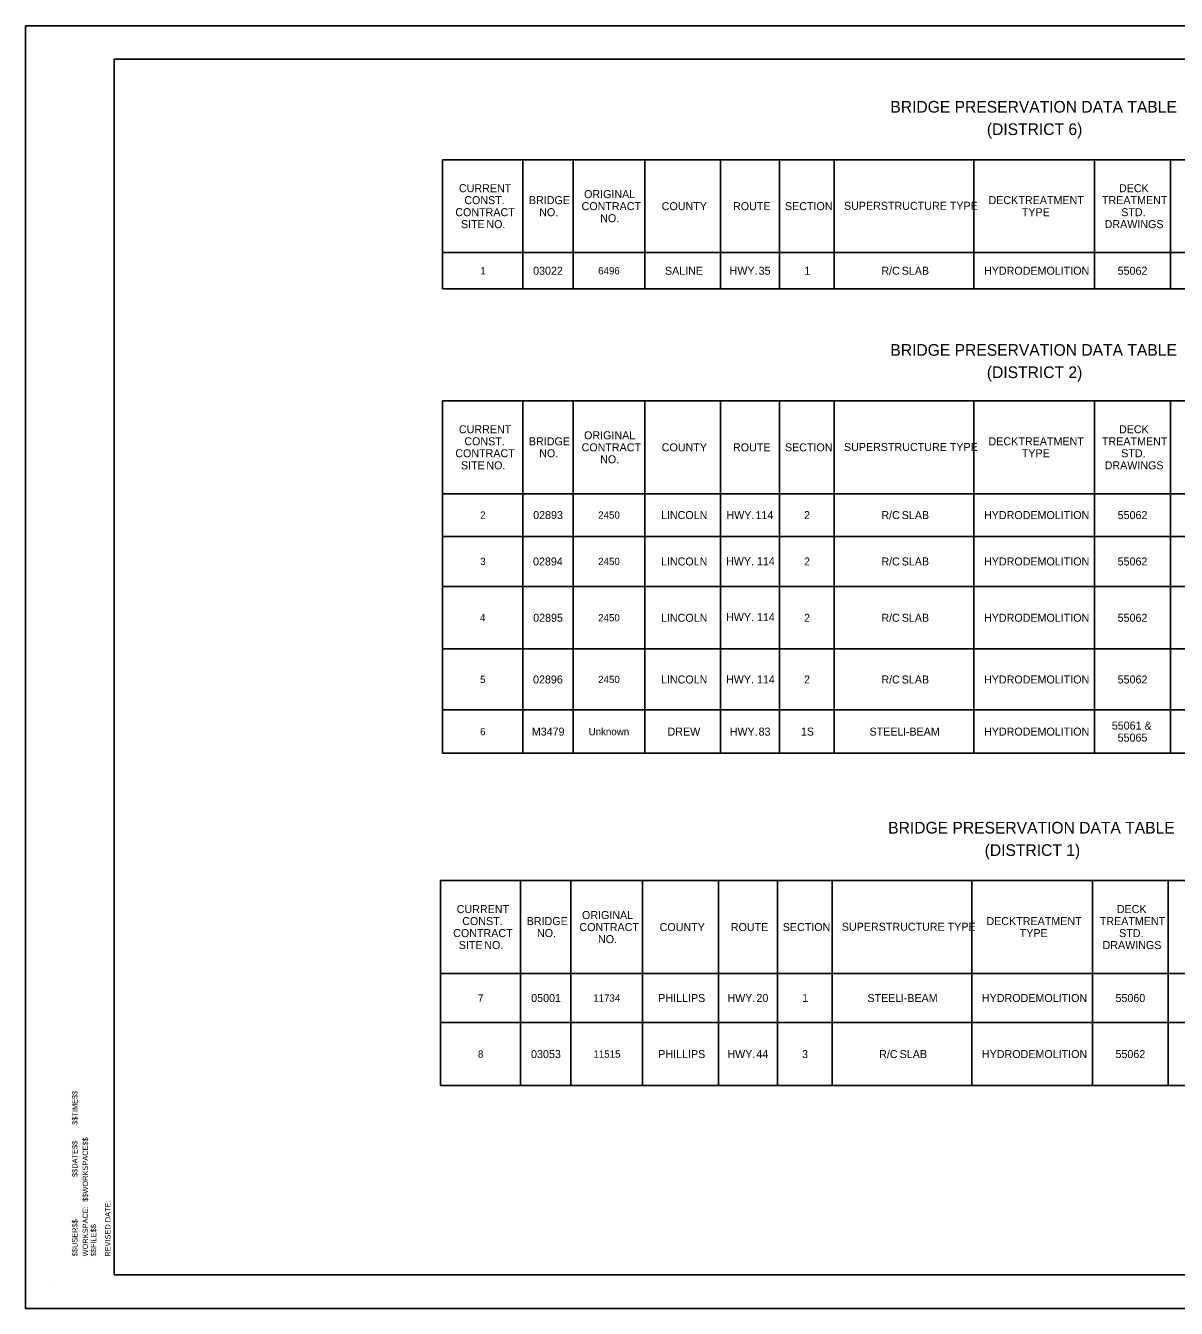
# Model space of a CAD drawing. Extents: x 16 to 1228740, y 11 to 152440.
# Drawn here: x 15.657 to 17.302, y 10.709 to 12.543 of the extents above; entities that cross this region are included whole.
import ezdxf

# ---------------------------------------------------------------- set-up
doc = ezdxf.new("R2010")
doc.units = 0
doc.layers.add('B_Text', color=7, linetype='Continuous')
doc.layers.add('R_Border', color=7, linetype='Continuous')

msp = doc.modelspace()

# ---------------------------------------------------------------- linework, layer by layer
at = {"layer": 'B_Text'}
for p, q in [((16.2529, 12.3512), (16.2529, 12.3512)), ((16.2529, 12.1667), (16.2529, 12.3512)), ((16.2529, 12.3512), (17.9726, 12.3512)), ((16.3674, 12.1667), (16.3674, 12.3512)), ((16.4394, 12.1667), (16.4394, 12.3512)), ((16.5419, 12.1667), (16.5419, 12.3512)), ((16.6504, 12.1667), (16.6504, 12.3512)), ((16.7345, 12.1667), (16.7345, 12.3512)), ((16.8126, 12.1667), (16.8126, 12.3512)), ((17.0124, 12.1667), (17.0124, 12.3512)), ((17.1847, 12.1667), (17.1847, 12.3512)), ((17.2932, 12.1667), (17.2932, 12.3512)), ((16.2529, 12.2184), (17.9726, 12.2184)), ((16.2529, 12.2184), (17.9726, 12.2184)), ((16.2529, 12.1667), (17.9726, 12.1667)), ((16.2529, 12.0066), (16.2529, 12.0066)), ((16.2529, 11.5029), (16.2529, 12.0066)), ((16.2529, 12.0066), (17.9726, 12.0066)), ((16.3674, 11.5029), (16.3674, 12.0066)), ((16.4394, 11.5029), (16.4394, 12.0066)), ((16.5419, 11.5029), (16.5419, 12.0066)), ((16.6504, 11.5029), (16.6504, 12.0066)), ((16.7345, 11.5029), (16.7345, 12.0066)), ((16.8126, 11.5029), (16.8126, 12.0066)), ((17.0124, 11.5029), (17.0124, 12.0066)), ((17.1847, 11.5029), (17.1847, 12.0066)), ((17.2932, 11.5029), (17.2932, 12.0066)), ((16.2529, 11.8737), (17.9726, 11.8737)), ((16.2529, 11.8129), (17.9726, 11.8129)), ((16.2529, 11.7412), (17.9726, 11.7412)), ((16.2529, 11.652), (17.9726, 11.652)), ((16.2529, 11.5647), (17.9726, 11.5647)), ((16.2529, 11.5029), (17.9726, 11.5029)), ((16.2498, 11.3208), (16.2498, 11.3208)), ((16.2498, 11.0278), (16.2498, 11.3208)), ((16.2498, 11.3208), (17.9757, 11.3208)), ((16.3644, 11.0278), (16.3644, 11.3208)), ((16.4364, 11.0278), (16.4364, 11.3208)), ((16.5388, 11.0278), (16.5388, 11.3208)), ((16.6473, 11.0278), (16.6473, 11.3208)), ((16.7315, 11.0278), (16.7315, 11.3208)), ((16.8096, 11.0278), (16.8096, 11.3208)), ((17.0093, 11.0278), (17.0093, 11.3208)), ((17.1817, 11.0278), (17.1817, 11.3208)), ((17.2902, 11.0278), (17.2902, 11.3208)), ((16.2498, 11.188), (17.9757, 11.188)), ((16.2498, 11.188), (17.9757, 11.188)), ((16.2498, 11.118), (17.9757, 11.118)), ((16.2498, 11.0278), (17.9757, 11.0278))]:
    msp.add_line(p, q, dxfattribs=at)
at = {"layer": 'R_Border'}
for p, q in [((15.7833, 12.4948), (18.4422, 12.4948)), ((15.7833, 10.7576), (15.7833, 12.4948)), ((15.6959, 10.7451), (15.6959, 10.7451)), ((18.4422, 10.7576), (15.7833, 10.7576))]:
    msp.add_line(p, q, dxfattribs=at)
msp.add_lwpolyline([(15.6569, 12.5428), (18.4903, 12.5428), (18.4903, 10.7095), (15.6569, 10.7095)], close=True, dxfattribs=at)

# ---------------------------------------------------------------- texts
at = {"layer": 'B_Text'}
for s, p in [('BRIDGE PRESERVATION DATA TABLE ', (16.893, 12.4185)), ('(DISTRICT 6)', (17.0309, 12.3865)), ('BRIDGE PRESERVATION DATA TABLE ', (16.893, 12.071)), ('(DISTRICT 2)', (17.0309, 12.0391)), ('BRIDGE PRESERVATION DATA TABLE ', (16.8899, 11.3881)), ('(DISTRICT 1)', (17.0278, 11.3561))]:
    msp.add_text(s, height=0.0167, rotation=360, dxfattribs=at).set_placement(p)
for s, height, p in [('CURRENT', 0.01144, (16.2763, 12.3048)), ('ORIGINAL', 0.01144, (16.4552, 12.2963)), ('DECK', 0.01144, (17.2198, 12.3048)), ('CONST.', 0.01144, (16.284, 12.2877)), ('BRIDGE', 0.01144, (16.3763, 12.2877)), ('CONTRACT', 0.01144, (16.4516, 12.2791)), ('COUNTY', 0.01144, (16.5662, 12.2791)), ('ROUTE', 0.01144, (16.6681, 12.2791)), ('SECTION', 0.01144, (16.7423, 12.2791)), ('SUPERSTRUCTURE TYPE', 0.01144, (16.8267, 12.2796)), ('DECK', 0.01144, (17.0333, 12.2877)), (' TREATMENT', 0.01144, (17.0718, 12.2877)), ('TREATMENT', 0.01144, (17.1955, 12.2877)), ('CONTRACT', 0.01144, (16.2711, 12.2705)), ('NO.', 0.01144, (16.391, 12.2705)), ('NO.', 0.01144, (16.4782, 12.2619)), ('TYPE', 0.01144, (17.0809, 12.2705)), ('STD.', 0.01144, (17.223, 12.2705)), ('SITE', 0.01144, (16.2792, 12.2534)), (' NO.', 0.01144, (16.3113, 12.2534)), ('DRAWINGS', 0.01144, (17.1993, 12.2534)), ('1', 0.0104, (16.3068, 12.1873)), ('03022', 0.01144, (16.3823, 12.1868)), ('6496', 0.0104, (16.4753, 12.1873)), ('SALINE', 0.01144, (16.5708, 12.1868)), ('HWY.', 0.01144, (16.6632, 12.1868)), (' 35', 0.01144, (16.7004, 12.1868)), ('1', 0.0114, (16.7699, 12.1868)), ('R/C', 0.01144, (16.8801, 12.1868)), (' SLAB', 0.01144, (16.905, 12.1868)), ('HYDRODEMOLITION', 0.01144, (17.0269, 12.1868)), ('55062', 0.01144, (17.2179, 12.1868)), ('CURRENT', 0.01144, (16.2763, 11.9602)), ('DECK', 0.01144, (17.2198, 11.9602)), ('CONST.', 0.01144, (16.284, 11.943)), ('BRIDGE', 0.01144, (16.3763, 11.943)), ('ORIGINAL', 0.01144, (16.4552, 11.9516)), ('DECK', 0.01144, (17.0333, 11.943)), (' TREATMENT', 0.01144, (17.0718, 11.943)), ('TREATMENT', 0.01144, (17.1955, 11.943)), ('CONTRACT', 0.01144, (16.2711, 11.9259)), ('NO.', 0.01144, (16.391, 11.9259)), ('CONTRACT', 0.01144, (16.4516, 11.9344)), ('COUNTY', 0.01144, (16.5662, 11.9344)), ('ROUTE', 0.01144, (16.6681, 11.9344)), ('SECTION', 0.01144, (16.7423, 11.9344)), ('SUPERSTRUCTURE TYPE', 0.01144, (16.8267, 11.9349)), ('TYPE', 0.01144, (17.0809, 11.9259)), ('STD.', 0.01144, (17.223, 11.9259)), ('SITE', 0.01144, (16.2792, 11.9087)), (' NO.', 0.01144, (16.3113, 11.9087)), ('NO.', 0.01144, (16.4782, 11.9173)), ('DRAWINGS', 0.01144, (17.1993, 11.9087)), ('2', 0.0104, (16.3066, 11.8381)), ('02893', 0.01144, (16.3824, 11.8376)), ('2450', 0.0104, (16.4753, 11.8381)), ('LINCOLN', 0.01144, (16.5651, 11.8376)), ('HWY.', 0.01144, (16.6587, 11.8376)), (' 114', 0.01144, (16.6959, 11.8376)), ('2', 0.0114, (16.7696, 11.8376)), ('R/C', 0.01144, (16.8801, 11.8376)), (' SLAB', 0.01144, (16.905, 11.8376)), ('HYDRODEMOLITION', 0.01144, (17.0269, 11.8376)), ('55062', 0.01144, (17.2179, 11.8376)), ('3', 0.0104, (16.3067, 11.7718)), ('02894', 0.01144, (16.3822, 11.7713)), ('2450', 0.0104, (16.4753, 11.7718)), ('LINCOLN', 0.01144, (16.5651, 11.7713)), ('HWY. 114', 0.01144, (16.6581, 11.7717)), ('2', 0.0114, (16.7696, 11.7713)), ('R/C', 0.01144, (16.8801, 11.7713)), (' SLAB', 0.01144, (16.905, 11.7713)), ('HYDRODEMOLITION', 0.01144, (17.0269, 11.7713)), ('55062', 0.01144, (17.2179, 11.7713)), ('4', 0.0104, (16.3064, 11.6914)), ('02895', 0.01144, (16.3824, 11.6908)), ('2450', 0.0104, (16.4753, 11.6914)), ('LINCOLN', 0.01144, (16.5651, 11.6908)), ('HWY. 114', 0.01144, (16.6581, 11.6917)), ('2', 0.0114, (16.7696, 11.6908)), ('R/C', 0.01144, (16.8801, 11.6908)), (' SLAB', 0.01144, (16.905, 11.6908)), ('HYDRODEMOLITION', 0.01144, (17.0269, 11.6908)), ('55062', 0.01144, (17.2179, 11.6908)), ('5', 0.0104, (16.3066, 11.6032)), ('02896', 0.01144, (16.3822, 11.6026)), ('2450', 0.0104, (16.4753, 11.6032)), ('LINCOLN', 0.01144, (16.5651, 11.6026)), ('HWY. 114', 0.01144, (16.6581, 11.6027)), ('2', 0.0114, (16.7696, 11.6026)), ('R/C', 0.01144, (16.8801, 11.6026)), (' SLAB', 0.01144, (16.905, 11.6026)), ('HYDRODEMOLITION', 0.01144, (17.0269, 11.6026)), ('55062', 0.01144, (17.2179, 11.6026)), ('6', 0.0104, (16.3065, 11.5286)), ('M3479', 0.01144, (16.3805, 11.5281)), ('Unknown', 0.0104, (16.4617, 11.5286)), ('DREW', 0.01144, (16.5745, 11.5281)), ('HWY.', 0.01144, (16.6633, 11.5281)), (' 83', 0.01144, (16.7004, 11.5281)), ('1S', 0.01144, (16.7651, 11.5281)), ('STEEL', 0.01144, (16.8633, 11.5281)), (' I-BEAM', 0.01144, (16.9067, 11.5281)), ('HYDRODEMOLITION', 0.01144, (17.0269, 11.5281)), ('55061 &', 0.01144, (17.2095, 11.5367)), ('55065', 0.01144, (17.2179, 11.5195)), ('CURRENT', 0.01144, (16.2732, 11.2744)), ('ORIGINAL', 0.01144, (16.4522, 11.2659)), ('DECK', 0.01144, (17.2167, 11.2744)), ('CONST.', 0.01144, (16.281, 11.2573)), ('BRIDGE', 0.01144, (16.3732, 11.2573)), ('CONTRACT', 0.01144, (16.4486, 11.2487)), ('COUNTY', 0.01144, (16.5632, 11.2487)), ('ROUTE', 0.01144, (16.665, 11.2487)), ('SECTION', 0.01144, (16.7392, 11.2487)), ('SUPERSTRUCTURE TYPE', 0.01144, (16.8236, 11.2492)), ('DECK', 0.01144, (17.0303, 11.2573)), (' TREATMENT', 0.01144, (17.0687, 11.2573)), ('TREATMENT', 0.01144, (17.1924, 11.2573)), ('CONTRACT', 0.01144, (16.2681, 11.2401)), ('NO.', 0.01144, (16.3879, 11.2401)), ('NO.', 0.01144, (16.4751, 11.2315)), ('TYPE', 0.01144, (17.0779, 11.2401)), ('STD.', 0.01144, (17.22, 11.2401)), ('SITE', 0.01144, (16.2761, 11.223)), (' NO.', 0.01144, (16.3083, 11.223)), ('DRAWINGS', 0.01144, (17.1963, 11.223)), ('7', 0.0104, (16.3035, 11.1478)), ('05001', 0.01144, (16.3796, 11.1473)), ('11734', 0.0104, (16.4683, 11.1478)), ('PHILLIPS', 0.01144, (16.5612, 11.1473)), ('HWY.', 0.01144, (16.6601, 11.1473)), (' 20', 0.01144, (16.6973, 11.1473)), ('1', 0.0114, (16.7669, 11.1473)), ('STEEL', 0.01144, (16.8602, 11.1473)), (' I-BEAM', 0.01144, (16.9036, 11.1473)), ('HYDRODEMOLITION', 0.01144, (17.0239, 11.1473)), ('55060', 0.01144, (17.2148, 11.1473)), ('8', 0.0104, (16.3035, 11.0677)), ('03053', 0.01144, (16.3794, 11.0672)), ('11515', 0.0104, (16.4685, 11.0677)), ('PHILLIPS', 0.01144, (16.5612, 11.0672)), ('HWY.', 0.01144, (16.66, 11.0672)), (' 44', 0.01144, (16.6971, 11.0672)), ('3', 0.0114, (16.7667, 11.0672)), ('R/C', 0.01144, (16.877, 11.0672)), (' SLAB', 0.01144, (16.902, 11.0672)), ('HYDRODEMOLITION', 0.01144, (17.0239, 11.0672)), ('55062', 0.01144, (17.2148, 11.0672))]:
    msp.add_text(s, height=height, dxfattribs=at).set_placement(p)
at = {"layer": 'R_Border'}
for s, p in [('$$TIME$$', (15.7311, 10.9718)), ('$$DATE$$', (15.7311, 10.8973)), ('$$WORKSPACE$$', (15.746, 10.8618)), ('REVISED DATE:', (15.7782, 10.7833)), ('WORKSPACE:', (15.746, 10.7838)), ('$$USER$$', (15.7311, 10.7839)), ('$$FILE$$', (15.7578, 10.7839))]:
    msp.add_text(s, height=0.00765, rotation=90, dxfattribs=at).set_placement(p)

doc.saveas('drawing.dxf')
